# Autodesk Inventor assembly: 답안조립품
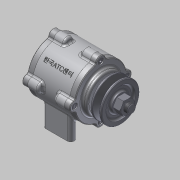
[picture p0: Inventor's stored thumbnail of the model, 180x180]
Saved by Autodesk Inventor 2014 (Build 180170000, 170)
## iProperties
Created: 2015-03
Part Number: 답안조립품
Document SubType Name: Assembly
Designer: MYHOME
Author: MYHOME
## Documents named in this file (11)
- C:\Documents and Settings\MYHOME\바탕 화면\450306V1006\답안조립품.iam
- C:\Documents and Settings\MYHOME\바탕 화면\450306V1006\본체.ipt
- C:\Documents and Settings\MYHOME\바탕 화면\450306V1006\커버.ipt
- C:\Documents and Settings\MYHOME\바탕 화면\450306V1006\커버2.ipt
- C:\Documents and Settings\MYHOME\바탕 화면\450306V1006\M 4 x 12.ipt
- C:\Documents and Settings\MYHOME\바탕 화면\450306V1006\오일실.ipt
- C:\Documents and Settings\MYHOME\바탕 화면\450306V1006\축.ipt
- C:\Documents and Settings\MYHOME\바탕 화면\450306V1006\키(4 x 4 x 12).ipt
- C:\Documents and Settings\MYHOME\바탕 화면\450306V1006\베어링 6204.ipt
- C:\Documents and Settings\MYHOME\바탕 화면\450306V1006\V벨트풀리.ipt
- C:\Documents and Settings\MYHOME\바탕 화면\450306V1006\너트 M12x1.25.ipt
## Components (14 placed, 6 different names)
1. KS B 2804 D D - 20 32 8:1
2. KS B 1311 (I) 4 x 4 x 12:1
3. KS B 2023 6204 - 20 x 47 x 14:1 — 각도:1
4. KS B 2023 6204 - 20 x 47 x 14:2 — 각도:2
5. 그루브 풀리1:1
6. KS B 1012 클래스 1 일반 - 미터 M12x1.25:1 — 각도:3
7. KS B 1003 - 미터 M 4 x 12:2
8. KS B 1003 - 미터 M 4 x 12:3
9. KS B 1003 - 미터 M 4 x 12:4
10. KS B 1003 - 미터 M 4 x 12:5
11. KS B 1003 - 미터 M 4 x 12:1
12. KS B 1003 - 미터 M 4 x 12:6
13. KS B 1003 - 미터 M 4 x 12:7
14. KS B 1003 - 미터 M 4 x 12:8
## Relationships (3: Angle 3)
- 각도:1 [Angle]: KS B 2023 6204 - 20 x 47 x 14:1
- 각도:2 [Angle]: KS B 2023 6204 - 20 x 47 x 14:2
- 각도:3 [Angle]: KS B 1012 클래스 1 일반 - 미터 M12x1.25:1
